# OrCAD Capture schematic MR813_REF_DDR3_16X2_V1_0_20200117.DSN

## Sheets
1 08 DDR3-16X2: size A3; title: R818_PER1_DDR3_16X2; rev: 0.1; note: 09 DDR3-16X2
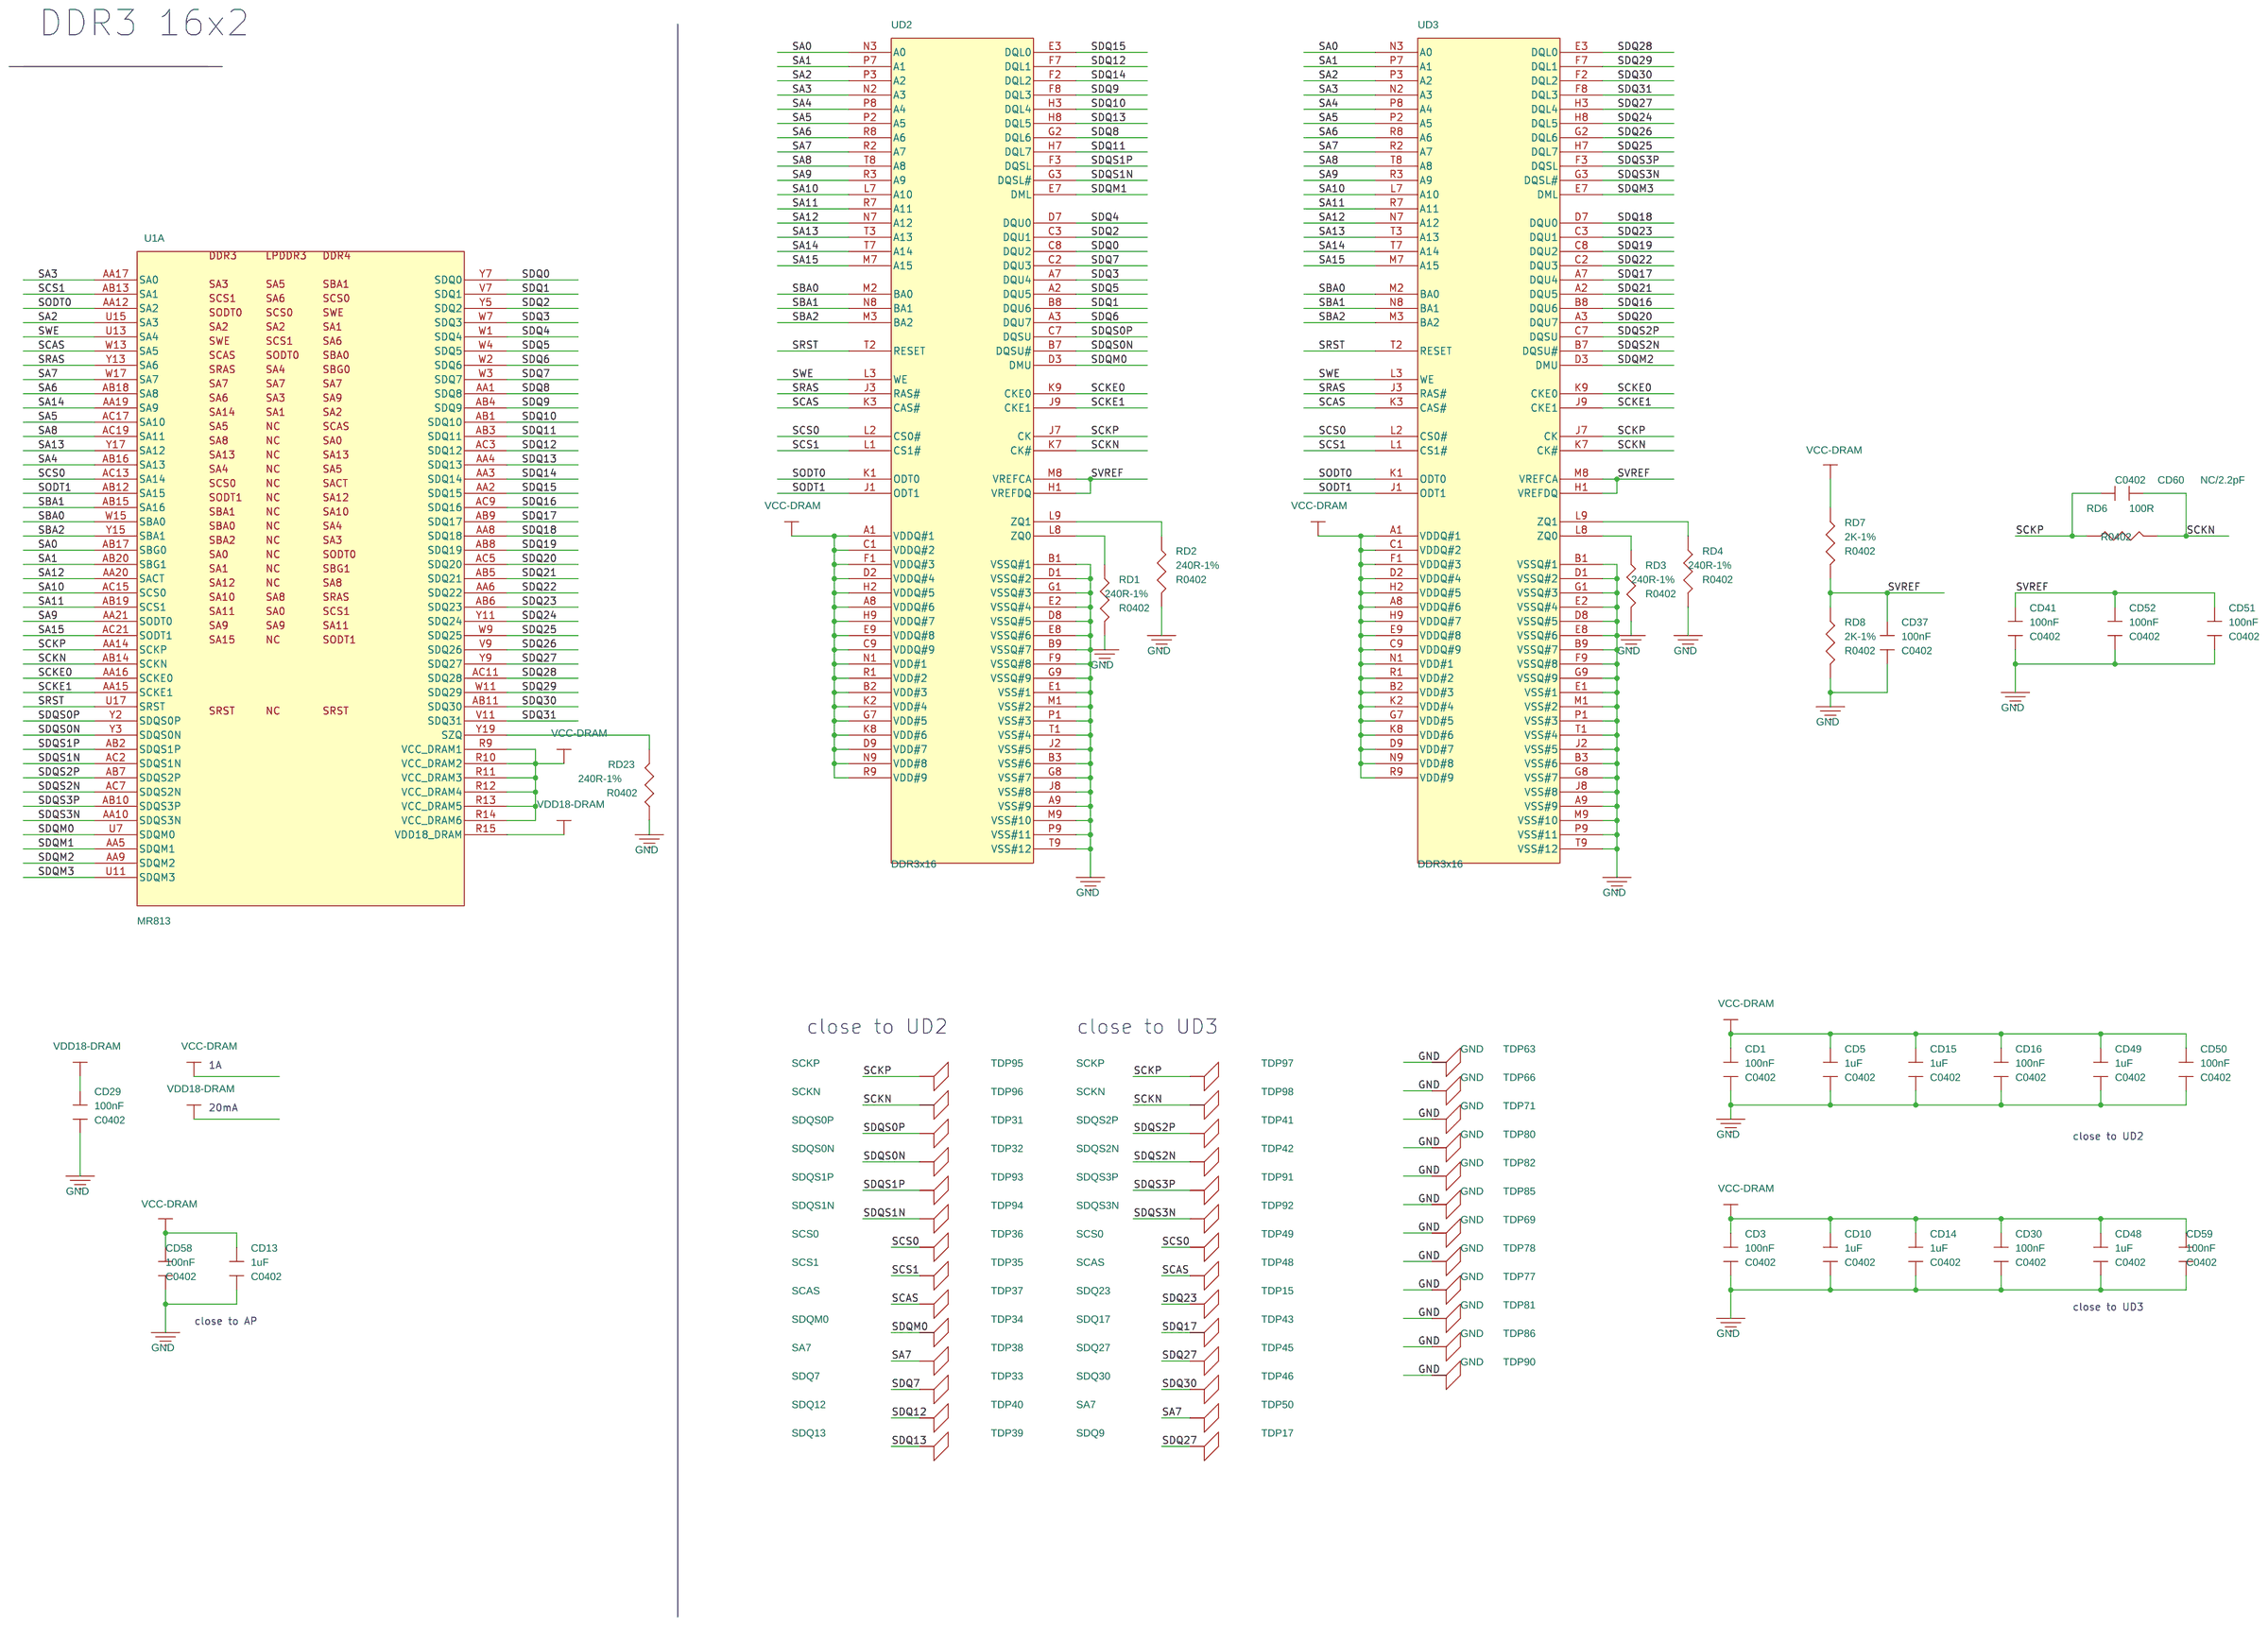
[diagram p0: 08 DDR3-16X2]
2 06 SOC-SYS: size A3; title: R818_REF_DDR3_16X2; note: 07 SOC-SYS
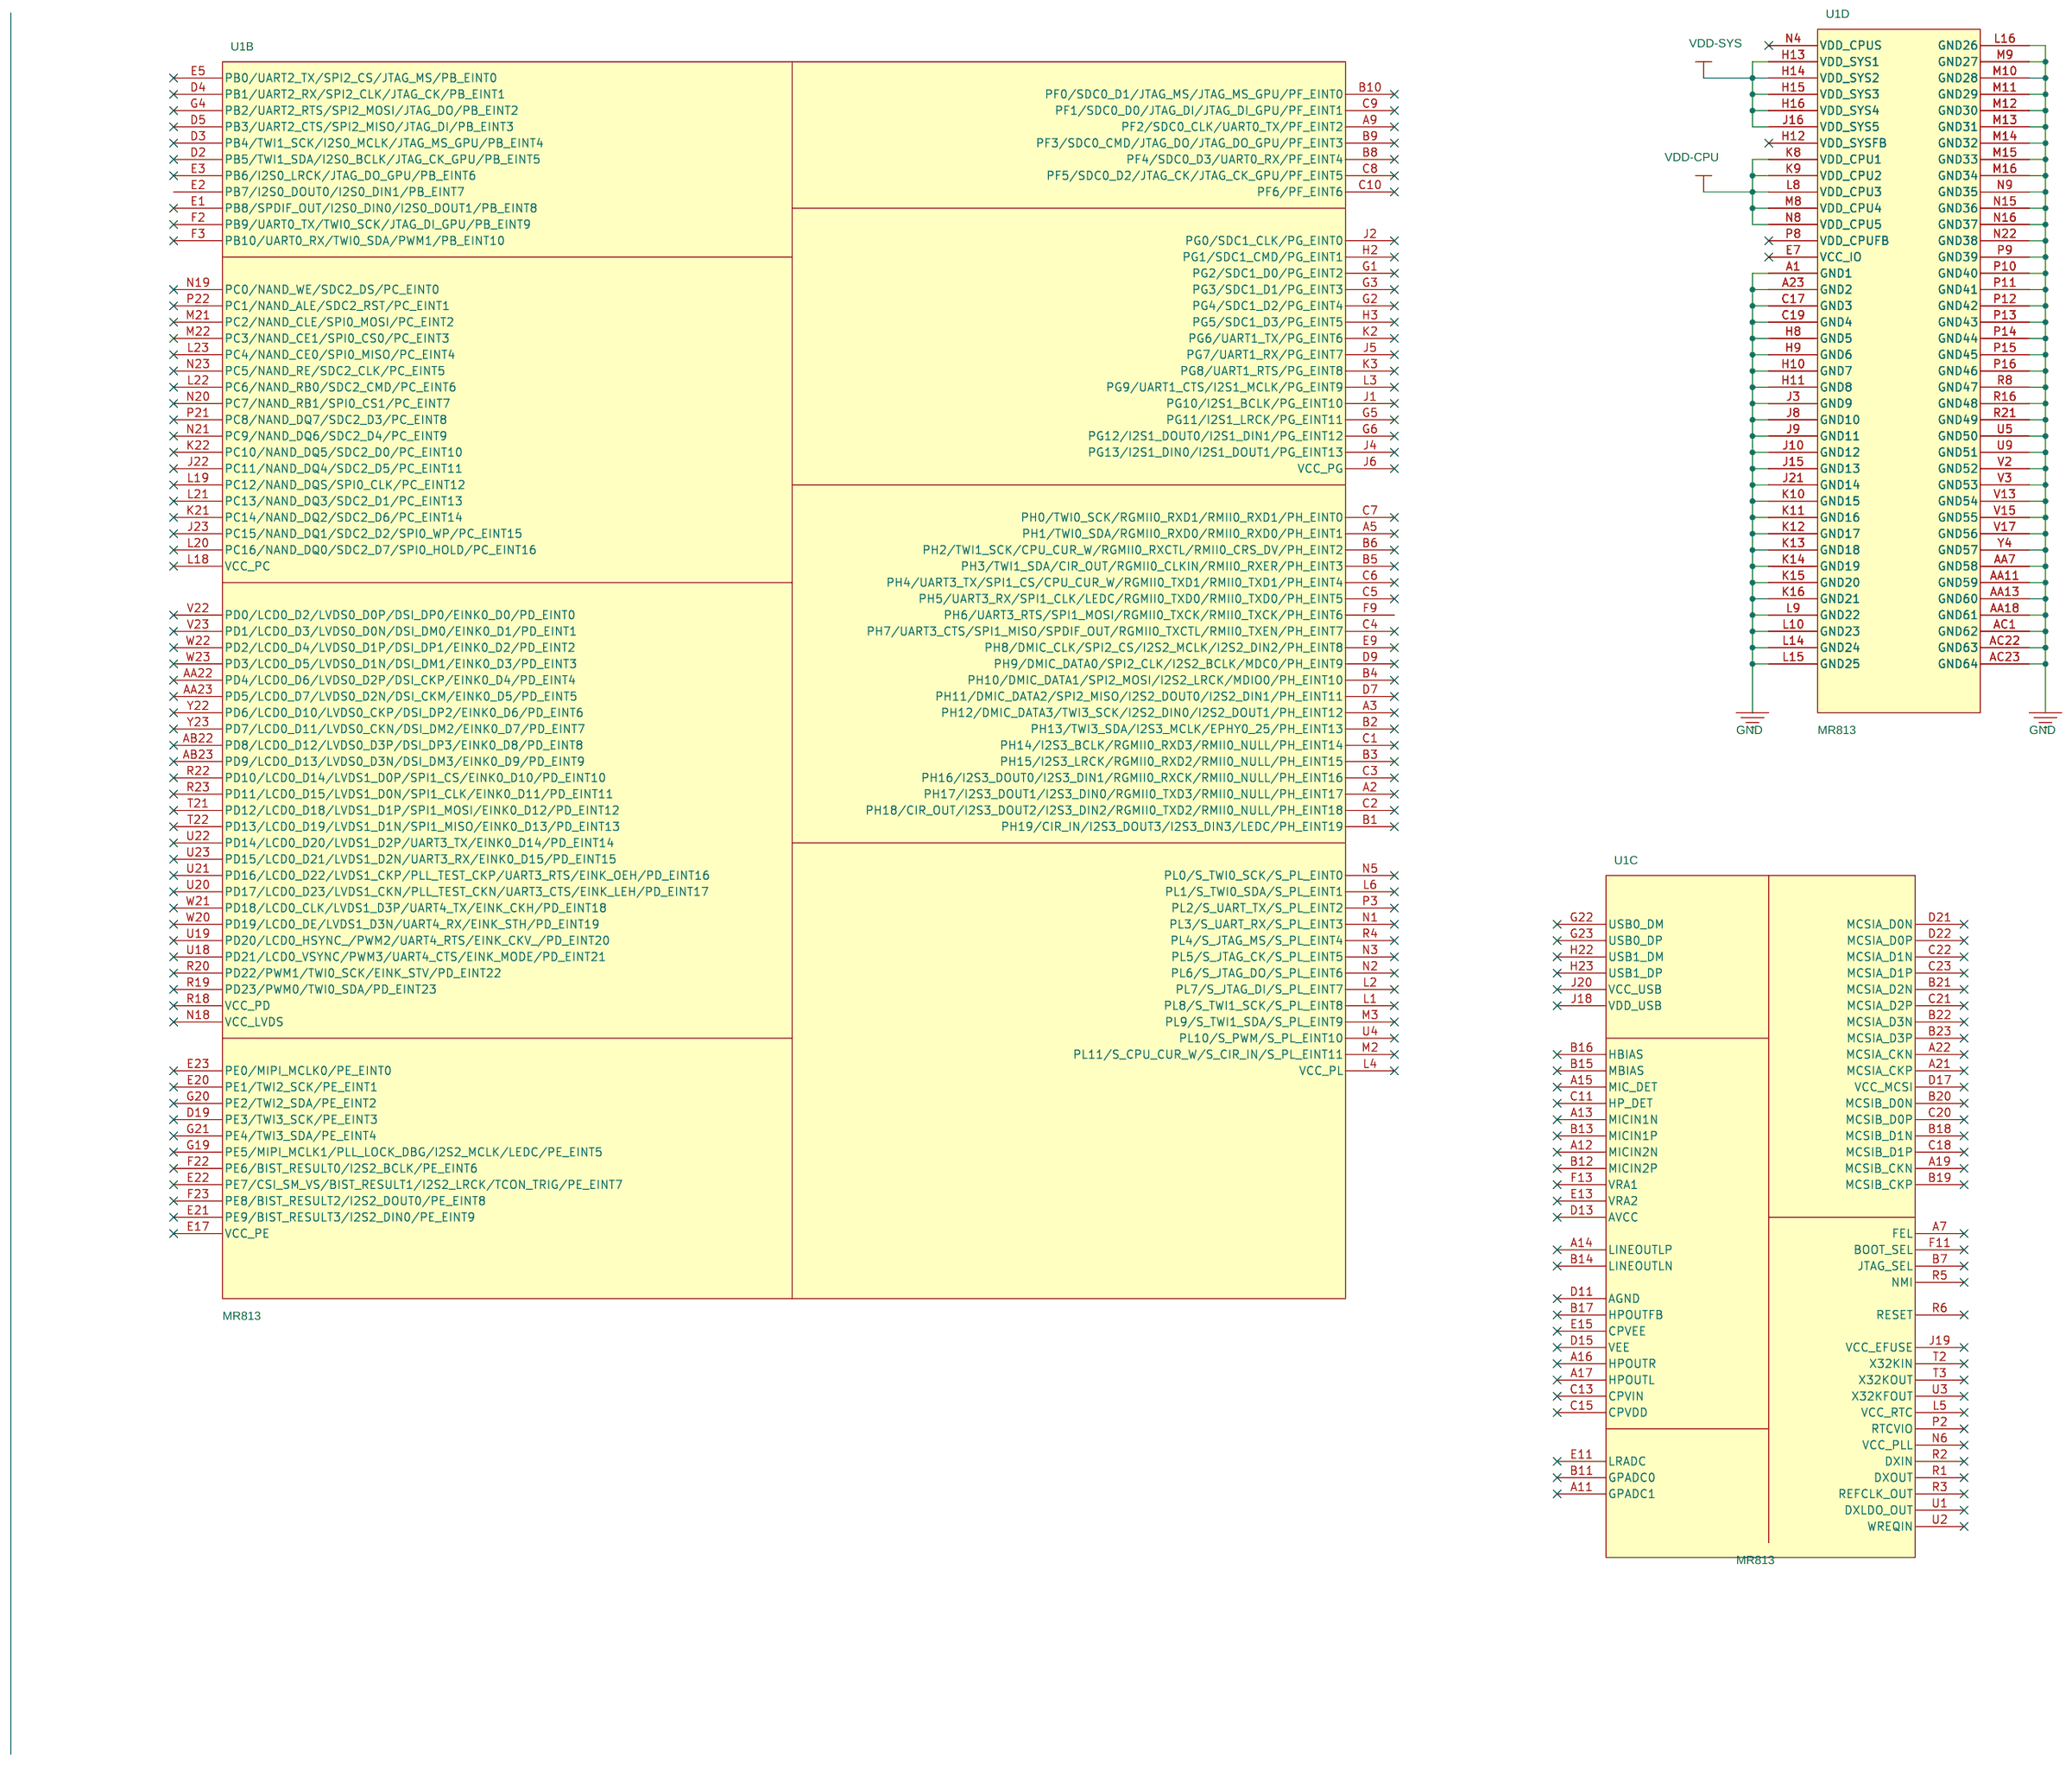
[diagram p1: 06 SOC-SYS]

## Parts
sheet 06 SOC-SYS
U1  MR813  [BGA346P50B1200_1200H114]  (sections A,B,C,D)
sheet 08 DDR3-16X2
CD1  100nF  [C0402]
CD3  100nF  [C0402]
CD5  1uF  [C0402]
CD10  1uF  [C0402]
CD13  1uF  [C0402]
CD14  1uF  [C0402]
CD15  1uF  [C0402]
CD16  100nF  [C0402]
CD29  100nF  [C0402]
CD30  100nF  [C0402]
CD37  100nF  [C0402]
CD41  100nF  [C0402]
CD48  1uF  [C0402]
CD49  1uF  [C0402]
CD50  100nF  [C0402]
CD51  100nF  [C0402]
CD52  100nF  [C0402]
CD58  100nF  [C0402]
CD59  100nF  [C0402]
CD60  NC/2.2pF  [C0402]
RD1  240R-1%  [R0402]
RD2  240R-1%  [R0402]
RD3  240R-1%  [R0402]
RD4  240R-1%  [R0402]
RD6  100R  [R0402]
RD7  2K-1%  [R0402]
RD8  2K-1%  [R0402]
RD23  240R-1%  [R0402]
TDP15  SDQ23  [TP30]
TDP17  SDQ9  [TP30]
TDP31  SDQS0P  [TP3_8X10]
TDP32  SDQS0N  [TP3_8X10]
TDP33  SDQ7  [TP3_8X10]
TDP34  SDQM0  [TP3_8X10]
TDP35  SCS1  [TP30]
TDP36  SCS0  [TP30]
TDP37  SCAS  [TP30]
TDP38  SA7  [TP30]
TDP39  SDQ13  [TP30]
TDP40  SDQ12  [TP30]
TDP41  SDQS2P  [TP3_8X10]
TDP42  SDQS2N  [TP3_8X10]
TDP43  SDQ17  [TP3_8X10]
TDP45  SDQ27  [TP30]
TDP46  SDQ30  [TP30]
TDP48  SCAS  [TP30]
TDP49  SCS0  [TP30]
TDP50  SA7  [TP30]
TDP63  GND  [TP30]
TDP66  GND  [TP30]
TDP69  GND  [TP30]
TDP71  GND  [TP30]
TDP77  GND  [TP30]
TDP78  GND  [TP30]
TDP80  GND  [TP30]
TDP81  GND  [TP30]
TDP82  GND  [TP30]
TDP85  GND  [TP30]
TDP86  GND  [TP30]
TDP90  GND  [TP30]
TDP91  SDQS3P  [TP30]
TDP92  SDQS3N  [TP30]
TDP93  SDQS1P  [TP30]
TDP94  SDQS1N  [TP30]
TDP95  SCKP  [TP30]
TDP96  SCKN  [TP30]
TDP97  SCKP  [TP30]
TDP98  SCKN  [TP30]
UD2  DDR3x16  [BGA96P80B1000_1300H120]
UD3  DDR3x16  [BGA96P80B1000_1300H120]

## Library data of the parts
U1 = R818-BGA-200107_0
CD1 CD3 CD5 CD10 CD13-CD16 CD29 CD30 CD37 CD41 CD48-CD52 CD60 = C-C0402-X5R_1
CD58 CD59 = CAPACITOR_0: PAGE: 2; ROOM: LPDDR3
RD1-RD4 RD7 RD8 RD23 = R-R0402-1%_0
RD6 = R-R0402-5%_1
TDP15 TDP17 TDP31-TDP43 TDP45 TDP46 TDP48-TDP50 TDP63 TDP66 TDP69 TDP71 TDP77 TDP78 TDP80-TDP82 TDP85 TDP86 TDP90-TDP98 = TestPoint-on_wire
UD2 UD3 = DDR3-FBGA96_0

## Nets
GND: CD1.2 CD3.2 CD5.2 CD10.2 CD13.2 CD14.2 CD15.2 CD16.2 CD29.2 CD30.2 CD37.2 CD41.2 CD48.2 CD49.2 CD50.2 CD51.2 CD52.2 CD58.1 CD59.1 RD1.2 RD2.2 RD3.2 RD4.2 RD8.2 RD23.2 TDP63.1(TP) TDP66.1(TP) TDP69.1(TP) TDP71.1(TP) TDP77.1(TP) TDP78.1(TP) TDP80.1(TP) TDP81.1(TP) TDP82.1(TP) TDP85.1(TP) TDP86.1(TP) TDP90.1(TP) U1.A1(GND1) U1.A23(GND2) U1.AA7(GND58) U1.AA11(GND59) U1.AA13(GND60) U1.AA18(GND61) U1.AC1(GND62) U1.AC22(GND63) U1.AC23(GND64) U1.C17(GND3) U1.C19(GND4) U1.H8(GND5) U1.H9(GND6) U1.H10(GND7) U1.H11(GND8) U1.J3(GND9) U1.J8(GND10) U1.J9(GND11) U1.J10(GND12) U1.J15(GND13) U1.J21(GND14) U1.K10(GND15) U1.K11(GND16) U1.K12(GND17) U1.K13(GND18) U1.K14(GND19) U1.K15(GND20) U1.K16(GND21) U1.L9(GND22) U1.L10(GND23) U1.L14(GND24) U1.L15(GND25) U1.L16(GND26) U1.M9(GND27) U1.M10(GND28) U1.M11(GND29) U1.M12(GND30) U1.M13(GND31) U1.M14(GND32) U1.M15(GND33) U1.M16(GND34) U1.N9(GND35) U1.N15(GND36) U1.N16(GND37) U1.N22(GND38) U1.P9(GND39) U1.P10(GND40) U1.P11(GND41) U1.P12(GND42) U1.P13(GND43) U1.P14(GND44) U1.P15(GND45) U1.P16(GND46) U1.R8(GND47) U1.R16(GND48) U1.R21(GND49) U1.U5(GND50) U1.U9(GND51) U1.V2(GND52) U1.V3(GND53) U1.V13(GND54) U1.V15(GND55) U1.V17(GND56) U1.Y4(GND57) UD2.A9(VSS#9) UD2.B1(VSSQ#1) UD2.B3(VSS#6) UD2.B9(VSSQ#7) UD2.D1(VSSQ#2) UD2.D8(VSSQ#5) UD2.E1(VSS#1) UD2.E2(VSSQ#4) UD2.E8(VSSQ#6) UD2.F9(VSSQ#8) UD2.G1(VSSQ#3) UD2.G8(VSS#7) UD2.G9(VSSQ#9) UD2.J2(VSS#5) UD2.J8(VSS#8) UD2.M1(VSS#2) UD2.M9(VSS#10) UD2.P1(VSS#3) UD2.P9(VSS#11) UD2.T1(VSS#4) UD2.T9(VSS#12) UD3.A9(VSS#9) UD3.B1(VSSQ#1) UD3.B3(VSS#6) UD3.B9(VSSQ#7) UD3.D1(VSSQ#2) UD3.D8(VSSQ#5) UD3.E1(VSS#1) UD3.E2(VSSQ#4) UD3.E8(VSSQ#6) UD3.F9(VSSQ#8) UD3.G1(VSSQ#3) UD3.G8(VSS#7) UD3.G9(VSSQ#9) UD3.J2(VSS#5) UD3.J8(VSS#8) UD3.M1(VSS#2) UD3.M9(VSS#10) UD3.P1(VSS#3) UD3.P9(VSS#11) UD3.T1(VSS#4) UD3.T9(VSS#12)
VCC-DRAM: CD1.1 CD3.1 CD5.1 CD10.1 CD13.1 CD14.1 CD15.1 CD16.1 CD30.1 CD48.1 CD49.1 CD50.1 CD58.2 CD59.2 RD7.1 U1.R9(VCC_DRAM1) U1.R10(VCC_DRAM2) U1.R11(VCC_DRAM3) U1.R12(VCC_DRAM4) U1.R13(VCC_DRAM5) U1.R14(VCC_DRAM6) UD2.A1(VDDQ#1) UD2.A8(VDDQ#6) UD2.B2(VDD#3) UD2.C1(VDDQ#2) UD2.C9(VDDQ#9) UD2.D2(VDDQ#4) UD2.D9(VDD#7) UD2.E9(VDDQ#8) UD2.F1(VDDQ#3) UD2.G7(VDD#5) UD2.H2(VDDQ#5) UD2.H9(VDDQ#7) UD2.K2(VDD#4) UD2.K8(VDD#6) UD2.N1(VDD#1) UD2.N9(VDD#8) UD2.R1(VDD#2) UD2.R9(VDD#9) UD3.A1(VDDQ#1) UD3.A8(VDDQ#6) UD3.B2(VDD#3) UD3.C1(VDDQ#2) UD3.C9(VDDQ#9) UD3.D2(VDDQ#4) UD3.D9(VDD#7) UD3.E9(VDDQ#8) UD3.F1(VDDQ#3) UD3.G7(VDD#5) UD3.H2(VDDQ#5) UD3.H9(VDDQ#7) UD3.K2(VDD#4) UD3.K8(VDD#6) UD3.N1(VDD#1) UD3.N9(VDD#8) UD3.R1(VDD#2) UD3.R9(VDD#9)
VDD18-DRAM: CD29.1 U1.R15(VDD18_DRAM)
VDD-CPU: U1.K8(VDD_CPU1) U1.K9(VDD_CPU2) U1.L8(VDD_CPU3) U1.M8(VDD_CPU4) U1.N8(VDD_CPU5)
VDD-SYS: U1.H13(VDD_SYS1) U1.H14(VDD_SYS2) U1.H15(VDD_SYS3) U1.H16(VDD_SYS4) U1.J16(VDD_SYS5)
SA0: U1.AB17(SBG0) UD2.N3(A0) UD3.N3(A0)
SA1: U1.AB20(SBG1) UD2.P7(A1) UD3.P7(A1)
SA2: U1.U15(SA3) UD2.P3(A2) UD3.P3(A2)
SA3: U1.AA17(SA0) UD2.N2(A3) UD3.N2(A3)
SA4: U1.AB16(SA13) UD2.P8(A4) UD3.P8(A4)
SA5: U1.AC17(SA10) UD2.P2(A5) UD3.P2(A5)
SA6: U1.AB18(SA8) UD2.R8(A6) UD3.R8(A6)
SA7: TDP38.1(TP) TDP50.1(TP) U1.W17(SA7) UD2.R2(A7) UD3.R2(A7)
SA8: U1.AC19(SA11) UD2.T8(A8) UD3.T8(A8)
SA9: U1.AA21(SODT0) UD2.R3(A9) UD3.R3(A9)
SA10: U1.AC15(SCS0) UD2.L7(A10) UD3.L7(A10)
SA11: U1.AB19(SCS1) UD2.R7(A11) UD3.R7(A11)
SA12: U1.AA20(SACT) UD2.N7(A12) UD3.N7(A12)
SA13: U1.Y17(SA12) UD2.T3(A13) UD3.T3(A13)
SA14: U1.AA19(SA9) UD2.T7(A14) UD3.T7(A14)
SA15: U1.AC21(SODT1) UD2.M7(A15) UD3.M7(A15)
SBA0: U1.W15(SBA0) UD2.M2(BA0) UD3.M2(BA0)
SBA1: U1.AB15(SA16) UD2.N8(BA1) UD3.N8(BA1)
SBA2: U1.Y15(SBA1) UD2.M3(BA2) UD3.M3(BA2)
SCAS: TDP37.1(TP) TDP48.1(TP) U1.W13(SA5) UD2.K3(CAS#) UD3.K3(CAS#)
SCKE0: U1.AA16(SCKE0) UD2.K9(CKE0) UD3.K9(CKE0)
SCKE1: U1.AA15(SCKE1) UD2.J9(CKE1) UD3.J9(CKE1)
SCKN: CD60.2 RD6.2 TDP96.1(TP) TDP98.1(TP) U1.AB14(SCKN) UD2.K7(CK#) UD3.K7(CK#)
SCKP: CD60.1 RD6.1 TDP95.1(TP) TDP97.1(TP) U1.AA14(SCKP) UD2.J7(CK) UD3.J7(CK)
SCS0: TDP36.1(TP) TDP49.1(TP) U1.AC13(SA14) UD2.L2(CS0#) UD3.L2(CS0#)
SCS1: TDP35.1(TP) U1.AB13(SA1) UD2.L1(CS1#) UD3.L1(CS1#)
SDQ0: U1.Y7(SDQ0) UD2.C8(DQU2)
SDQ1: U1.V7(SDQ1) UD2.B8(DQU6)
SDQ2: U1.Y5(SDQ2) UD2.C3(DQU1)
SDQ3: U1.W7(SDQ3) UD2.A7(DQU4)
SDQ4: U1.W1(SDQ4) UD2.D7(DQU0)
SDQ5: U1.W4(SDQ5) UD2.A2(DQU5)
SDQ6: U1.W2(SDQ6) UD2.A3(DQU7)
SDQ7: TDP33.1(TP) U1.W3(SDQ7) UD2.C2(DQU3)
SDQ8: U1.AA1(SDQ8) UD2.G2(DQL6)
SDQ9: U1.AB4(SDQ9) UD2.F8(DQL3)
SDQ10: U1.AB1(SDQ10) UD2.H3(DQL4)
SDQ11: U1.AB3(SDQ11) UD2.H7(DQL7)
SDQ12: TDP40.1(TP) U1.AC3(SDQ12) UD2.F7(DQL1)
SDQ13: TDP39.1(TP) U1.AA4(SDQ13) UD2.H8(DQL5)
SDQ14: U1.AA3(SDQ14) UD2.F2(DQL2)
SDQ15: U1.AA2(SDQ15) UD2.E3(DQL0)
SDQ16: U1.AC9(SDQ16) UD3.B8(DQU6)
SDQ17: TDP43.1(TP) U1.AB9(SDQ17) UD3.A7(DQU4)
SDQ18: U1.AA8(SDQ18) UD3.D7(DQU0)
SDQ19: U1.AB8(SDQ19) UD3.C8(DQU2)
SDQ20: U1.AC5(SDQ20) UD3.A3(DQU7)
SDQ21: U1.AB5(SDQ21) UD3.A2(DQU5)
SDQ22: U1.AA6(SDQ22) UD3.C2(DQU3)
SDQ23: TDP15.1(TP) U1.AB6(SDQ23) UD3.C3(DQU1)
SDQ24: U1.Y11(SDQ24) UD3.H8(DQL5)
SDQ25: U1.W9(SDQ25) UD3.H7(DQL7)
SDQ26: U1.V9(SDQ26) UD3.G2(DQL6)
SDQ27: TDP17.1(TP) TDP45.1(TP) U1.Y9(SDQ27) UD3.H3(DQL4)
SDQ28: U1.AC11(SDQ28) UD3.E3(DQL0)
SDQ29: U1.W11(SDQ29) UD3.F7(DQL1)
SDQ30: TDP46.1(TP) U1.AB11(SDQ30) UD3.F2(DQL2)
SDQ31: U1.V11(SDQ31) UD3.F8(DQL3)
SDQM0: TDP34.1(TP) U1.U7(SDQM0) UD2.D3(DMU)
SDQM1: U1.AA5(SDQM1) UD2.E7(DML)
SDQM2: U1.AA9(SDQM2) UD3.D3(DMU)
SDQM3: U1.U11(SDQM3) UD3.E7(DML)
SDQS0N: TDP32.1(TP) U1.Y3(SDQS0N) UD2.B7(DQSU#)
SDQS0P: TDP31.1(TP) U1.Y2(SDQS0P) UD2.C7(DQSU)
SDQS1N: TDP94.1(TP) U1.AC2(SDQS1N) UD2.G3(DQSL#)
SDQS1P: TDP93.1(TP) U1.AB2(SDQS1P) UD2.F3(DQSL)
SDQS2N: TDP42.1(TP) U1.AC7(SDQS2N) UD3.B7(DQSU#)
SDQS2P: TDP41.1(TP) U1.AB7(SDQS2P) UD3.C7(DQSU)
SDQS3N: TDP92.1(TP) U1.AA10(SDQS3N) UD3.G3(DQSL#)
SDQS3P: TDP91.1(TP) U1.AB10(SDQS3P) UD3.F3(DQSL)
SODT0: U1.AA12(SA2) UD2.K1(ODT0) UD3.K1(ODT0)
SODT1: U1.AB12(SA15) UD2.J1(ODT1) UD3.J1(ODT1)
SRAS: U1.Y13(SA6) UD2.J3(RAS#) UD3.J3(RAS#)
SRST: U1.U17(SRST) UD2.T2(RESET) UD3.T2(RESET)
SVREF: CD37.1 CD41.1 CD51.1 CD52.1 RD7.2 RD8.1 UD2.H1(VREFDQ) UD2.M8(VREFCA) UD3.H1(VREFDQ) UD3.M8(VREFCA)
SWE: U1.U13(SA4) UD2.L3(WE) UD3.L3(WE)
N19162951: RD2.1 UD2.L9(ZQ1)
N19162953: RD1.1 UD2.L8(ZQ0)
N19163235: RD3.1 UD3.L8(ZQ0)
N19163239: RD4.1 UD3.L9(ZQ1)
N19640723: RD23.1 U1.Y19(SZQ)

Not connected (* = marked no-connect by the designer): U1 A2(PH17/I2S3_DOUT1/I2S3_DIN0/RGMII0_TXD3/RMII0_NULL/PH_EINT17)* A3(PH12/DMIC_DATA3/TWI3_SCK/I2S2_DIN0/I2S2_DOUT1/PH_EINT12)* A5(PH1/TWI0_SDA/RGMII0_RXD0/RMII0_RXD0/PH_EINT1)* A7(FEL)* A9(PF2/SDC0_CLK/UART0_TX/PF_EINT2)* A11(GPADC1)* A12(MICIN2N)* A13(MICIN1N)* A14(LINEOUTLP)* A15(MIC_DET)* A16(HPOUTR)* A17(HPOUTL)* A19(MCSIB_CKN)* A21(MCSIA_CKP)* A22(MCSIA_CKN)* AA22(PD4/LCD0_D6/LVDS0_D2P/DSI_CKP/EINK0_D4/PD_EINT4)* AA23(PD5/LCD0_D7/LVDS0_D2N/DSI_CKM/EINK0_D5/PD_EINT5)* AB22(PD8/LCD0_D12/LVDS0_D3P/DSI_DP3/EINK0_D8/PD_EINT8)* AB23(PD9/LCD0_D13/LVDS0_D3N/DSI_DM3/EINK0_D9/PD_EINT9)* B1(PH19/CIR_IN/I2S3_DOUT3/I2S3_DIN3/LEDC/PH_EINT19)* B2(PH13/TWI3_SDA/I2S3_MCLK/EPHY0_25/PH_EINT13)* B3(PH15/I2S3_LRCK/RGMII0_RXD2/RMII0_NULL/PH_EINT15)* B4(PH10/DMIC_DATA1/SPI2_MOSI/I2S2_LRCK/MDIO0/PH_EINT10)* B5(PH3/TWI1_SDA/CIR_OUT/RGMII0_CLKIN/RMII0_RXER/PH_EINT3)* B6(PH2/TWI1_SCK/CPU_CUR_W/RGMII0_RXCTL/RMII0_CRS_DV/PH_EINT2)* B7(JTAG_SEL)* B8(PF4/SDC0_D3/UART0_RX/PF_EINT4)* B9(PF3/SDC0_CMD/JTAG_DO/JTAG_DO_GPU/PF_EINT3)* B10(PF0/SDC0_D1/JTAG_MS/JTAG_MS_GPU/PF_EINT0)* B11(GPADC0)* B12(MICIN2P)* B13(MICIN1P)* B14(LINEOUTLN)* B15(MBIAS)* B16(HBIAS)* B17(HPOUTFB)* B18(MCSIB_D1N)* B19(MCSIB_CKP)* B20(MCSIB_D0N)* B21(MCSIA_D2N)* B22(MCSIA_D3N)* B23(MCSIA_D3P)* C1(PH14/I2S3_BCLK/RGMII0_RXD3/RMII0_NULL/PH_EINT14)* C2(PH18/CIR_OUT/I2S3_DOUT2/I2S3_DIN2/RGMII0_TXD2/RMII0_NULL/PH_EINT18)* C3(PH16/I2S3_DOUT0/I2S3_DIN1/RGMII0_RXCK/RMII0_NULL/PH_EINT16)* C4(PH7/UART3_CTS/SPI1_MISO/SPDIF_OUT/RGMII0_TXCTL/RMII0_TXEN/PH_EINT7)* C5(PH5/UART3_RX/SPI1_CLK/LEDC/RGMII0_TXD0/RMII0_TXD0/PH_EINT5)* C6(PH4/UART3_TX/SPI1_CS/CPU_CUR_W/RGMII0_TXD1/RMII0_TXD1/PH_EINT4)* C7(PH0/TWI0_SCK/RGMII0_RXD1/RMII0_RXD1/PH_EINT0)* C8(PF5/SDC0_D2/JTAG_CK/JTAG_CK_GPU/PF_EINT5)* C9(PF1/SDC0_D0/JTAG_DI/JTAG_DI_GPU/PF_EINT1)* C10(PF6/PF_EINT6)* C11(HP_DET)* C13(CPVIN)* C15(CPVDD)* C18(MCSIB_D1P)* C20(MCSIB_D0P)* C21(MCSIA_D2P)* C22(MCSIA_D1N)* C23(MCSIA_D1P)* D2(PB5/TWI1_SDA/I2S0_BCLK/JTAG_CK_GPU/PB_EINT5)* D3(PB4/TWI1_SCK/I2S0_MCLK/JTAG_MS_GPU/PB_EINT4)* D4(PB1/UART2_RX/SPI2_CLK/JTAG_CK/PB_EINT1)* D5(PB3/UART2_CTS/SPI2_MISO/JTAG_DI/PB_EINT3)* D7(PH11/DMIC_DATA2/SPI2_MISO/I2S2_DOUT0/I2S2_DIN1/PH_EINT11)* D9(PH9/DMIC_DATA0/SPI2_CLK/I2S2_BCLK/MDC0/PH_EINT9)* D11(AGND)* D13(AVCC)* D15(VEE)* D17(VCC_MCSI)* D19(PE3/TWI3_SCK/PE_EINT3)* D21(MCSIA_D0N)* D22(MCSIA_D0P)* E1(PB8/SPDIF_OUT/I2S0_DIN0/I2S0_DOUT1/PB_EINT8)* E2(PB7/I2S0_DOUT0/I2S0_DIN1/PB_EINT7) E3(PB6/I2S0_LRCK/JTAG_DO_GPU/PB_EINT6)* E5(PB0/UART2_TX/SPI2_CS/JTAG_MS/PB_EINT0)* E7(VCC_IO)* E9(PH8/DMIC_CLK/SPI2_CS/I2S2_MCLK/I2S2_DIN2/PH_EINT8)* E11(LRADC)* E13(VRA2)* E15(CPVEE)* E17(VCC_PE)* E20(PE1/TWI2_SCK/PE_EINT1)* E21(PE9/BIST_RESULT3/I2S2_DIN0/PE_EINT9)* E22(PE7/CSI_SM_VS/BIST_RESULT1/I2S2_LRCK/TCON_TRIG/PE_EINT7)* E23(PE0/MIPI_MCLK0/PE_EINT0)* F2(PB9/UART0_TX/TWI0_SCK/JTAG_DI_GPU/PB_EINT9)* F3(PB10/UART0_RX/TWI0_SDA/PWM1/PB_EINT10)* F9(PH6/UART3_RTS/SPI1_MOSI/RGMII0_TXCK/RMII0_TXCK/PH_EINT6) F11(BOOT_SEL)* F13(VRA1)* F22(PE6/BIST_RESULT0/I2S2_BCLK/PE_EINT6)* F23(PE8/BIST_RESULT2/I2S2_DOUT0/PE_EINT8)* G1(PG2/SDC1_D0/PG_EINT2)* G2(PG4/SDC1_D2/PG_EINT4)* G3(PG3/SDC1_D1/PG_EINT3)* G4(PB2/UART2_RTS/SPI2_MOSI/JTAG_DO/PB_EINT2)* G5(PG11/I2S1_LRCK/PG_EINT11)* G6(PG12/I2S1_DOUT0/I2S1_DIN1/PG_EINT12)* G19(PE5/MIPI_MCLK1/PLL_LOCK_DBG/I2S2_MCLK/LEDC/PE_EINT5)* G20(PE2/TWI2_SDA/PE_EINT2)* G21(PE4/TWI3_SDA/PE_EINT4)* G22(USB0_DM)* G23(USB0_DP)* H2(PG1/SDC1_CMD/PG_EINT1)* H3(PG5/SDC1_D3/PG_EINT5)* H12(VDD_SYSFB)* H22(USB1_DM)* H23(USB1_DP)* J1(PG10/I2S1_BCLK/PG_EINT10)* J2(PG0/SDC1_CLK/PG_EINT0)* J4(PG13/I2S1_DIN0/I2S1_DOUT1/PG_EINT13)* J5(PG7/UART1_RX/PG_EINT7)* J6(VCC_PG)* J18(VDD_USB)* J19(VCC_EFUSE)* J20(VCC_USB)* J22(PC11/NAND_DQ4/SDC2_D5/PC_EINT11)* J23(PC15/NAND_DQ1/SDC2_D2/SPI0_WP/PC_EINT15)* K2(PG6/UART1_TX/PG_EINT6)* K3(PG8/UART1_RTS/PG_EINT8)* K21(PC14/NAND_DQ2/SDC2_D6/PC_EINT14)* K22(PC10/NAND_DQ5/SDC2_D0/PC_EINT10)* L1(PL8/S_TWI1_SCK/S_PL_EINT8)* L2(PL7/S_JTAG_DI/S_PL_EINT7)* L3(PG9/UART1_CTS/I2S1_MCLK/PG_EINT9)* L4(VCC_PL)* L5(VCC_RTC)* L6(PL1/S_TWI0_SDA/S_PL_EINT1)* L18(VCC_PC)* L19(PC12/NAND_DQS/SPI0_CLK/PC_EINT12)* L20(PC16/NAND_DQ0/SDC2_D7/SPI0_HOLD/PC_EINT16)* L21(PC13/NAND_DQ3/SDC2_D1/PC_EINT13)* L22(PC6/NAND_RB0/SDC2_CMD/PC_EINT6)* L23(PC4/NAND_CE0/SPI0_MISO/PC_EINT4)* M2(PL11/S_CPU_CUR_W/S_CIR_IN/S_PL_EINT11)* M3(PL9/S_TWI1_SDA/S_PL_EINT9)* M21(PC2/NAND_CLE/SPI0_MOSI/PC_EINT2)* M22(PC3/NAND_CE1/SPI0_CS0/PC_EINT3)* N1(PL3/S_UART_RX/S_PL_EINT3)* N2(PL6/S_JTAG_DO/S_PL_EINT6)* N3(PL5/S_JTAG_CK/S_PL_EINT5)* N4(VDD_CPUS)* N5(PL0/S_TWI0_SCK/S_PL_EINT0)* N6(VCC_PLL)* N18(VCC_LVDS)* N19(PC0/NAND_WE/SDC2_DS/PC_EINT0)* N20(PC7/NAND_RB1/SPI0_CS1/PC_EINT7)* N21(PC9/NAND_DQ6/SDC2_D4/PC_EINT9)* N23(PC5/NAND_RE/SDC2_CLK/PC_EINT5)* P2(RTCVIO)* P3(PL2/S_UART_TX/S_PL_EINT2)* P8(VDD_CPUFB)* P21(PC8/NAND_DQ7/SDC2_D3/PC_EINT8)* P22(PC1/NAND_ALE/SDC2_RST/PC_EINT1)* R1(DXOUT)* R2(DXIN)* R3(REFCLK_OUT)* R4(PL4/S_JTAG_MS/S_PL_EINT4)* R5(NMI)* R6(RESET)* R18(VCC_PD)* R19(PD23/PWM0/TWI0_SDA/PD_EINT23)* R20(PD22/PWM1/TWI0_SCK/EINK_STV/PD_EINT22)* R22(PD10/LCD0_D14/LVDS1_D0P/SPI1_CS/EINK0_D10/PD_EINT10)* R23(PD11/LCD0_D15/LVDS1_D0N/SPI1_CLK/EINK0_D11/PD_EINT11)* T2(X32KIN)* T3(X32KOUT)* T21(PD12/LCD0_D18/LVDS1_D1P/SPI1_MOSI/EINK0_D12/PD_EINT12)* T22(PD13/LCD0_D19/LVDS1_D1N/SPI1_MISO/EINK0_D13/PD_EINT13)* U1(DXLDO_OUT)* U2(WREQIN)* U3(X32KFOUT)* U4(PL10/S_PWM/S_PL_EINT10)* U18(PD21/LCD0_VSYNC/PWM3/UART4_CTS/EINK_MODE/PD_EINT21)* U19(PD20/LCD0_HSYNC_/PWM2/UART4_RTS/EINK_CKV_/PD_EINT20)* U20(PD17/LCD0_D23/LVDS1_CKN/PLL_TEST_CKN/UART3_CTS/EINK_LEH/PD_EINT17)* U21(PD16/LCD0_D22/LVDS1_CKP/PLL_TEST_CKP/UART3_RTS/EINK_OEH/PD_EINT16)* U22(PD14/LCD0_D20/LVDS1_D2P/UART3_TX/EINK0_D14/PD_EINT14)* U23(PD15/LCD0_D21/LVDS1_D2N/UART3_RX/EINK0_D15/PD_EINT15)* V22(PD0/LCD0_D2/LVDS0_D0P/DSI_DP0/EINK0_D0/PD_EINT0)* V23(PD1/LCD0_D3/LVDS0_D0N/DSI_DM0/EINK0_D1/PD_EINT1)* W20(PD19/LCD0_DE/LVDS1_D3N/UART4_RX/EINK_STH/PD_EINT19)* W21(PD18/LCD0_CLK/LVDS1_D3P/UART4_TX/EINK_CKH/PD_EINT18)* W22(PD2/LCD0_D4/LVDS0_D1P/DSI_DP1/EINK0_D2/PD_EINT2)* W23(PD3/LCD0_D5/LVDS0_D1N/DSI_DM1/EINK0_D3/PD_EINT3)* Y22(PD6/LCD0_D10/LVDS0_CKP/DSI_DP2/EINK0_D6/PD_EINT6)* Y23(PD7/LCD0_D11/LVDS0_CKN/DSI_DM2/EINK0_D7/PD_EINT7)*

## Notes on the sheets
sheet 1
- DDR3 16x2
- close to UD2
- close to UD3
- 1A
- 20mA
- close to UD2
- close to UD3
- close to AP
